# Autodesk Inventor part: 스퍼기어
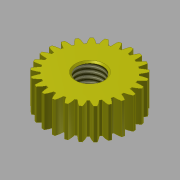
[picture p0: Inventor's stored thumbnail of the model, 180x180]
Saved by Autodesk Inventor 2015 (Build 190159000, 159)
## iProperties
Created: 2017-04
Part Number: 스퍼기어
Material: 강철
Document SubType Name: Modeling
Designer: mduedu
Categories: <?xml version="1.0" encoding="UTF-16"?> <MemberInstance><Categories><FamilyTemplate><FamilyTemplateParameter ValueType="xs:double" Id="1" ObjectReferenceKey="da
Density: 7.85 g/cm^3
Mass: 33.8546 g
Surface Area: 26.941 cm^2
Volume: 4.31269 cm^3
Appearance: 노란색
Author: mduedu
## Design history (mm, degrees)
sketch "Sketch1"
  geometry: C1 r 13.5 at (0, 0)
  constraints: 1 centre point
  dimensions: "d0" = 27 diameter of C1 (= da_da)
extrude "Extrusion1" new body sketch "Sketch1" distance "d1" = 10 (= da_b); taper "d2" = 0 deg
workplane "Work Plane2"
sketch "Sketch2"
  geometry: C1 r 13.5 at (0, 0) reference; C2 r 12.5 at (0, 0)
  constraints: 1 centre point, 1 coincident
  dimensions: "d3" = 25 diameter of C2 (= da_dw)
feature "피치 지름" sketch "Sketch2" dims "d4" = 10, "d5" = 0
workplane "Work Plane8"
workplane "Work Plane9"
feature "스퍼 기어" dims "da_b" = 10, "da_d" = 25, "da_aw" = 25, "da_da" = 27, "da_df" = 22.5, "da_dw" = 25, angle "da_beta" = 0 deg, "da_lefttooth" = 0, "da_righttooth" = 0
sketch "스케치3"
  geometry: C1 r 4.188 at (0, 0); 1 further point
  constraints: 1 centre point, 1 coincident
  dimensions: "d49" = 8.376 diameter of C1
extrude "돌출2" cut sketch "스케치3" stored distance "d50" = 10; taper "d51" = 0 deg
feature "스레드1" dims "d52" = 10, "d53" = 0
chamfer "모따기1" distance "d54" = 0.5; stored, may be unused: second distance "d55" = 2, angle "d56" = 45 deg
body "Solid1"
body "Srf1"
other parameters: "d16" = 25 (= da_aw), "d17" = 0, "d34" = 1.25664 (computed from da_z), "d39" = 0, "d41" = 0, "d43" = 25 (= da_aw), "d46" = 25 (= da_aw), "d47" = 0, "d48" = 0
